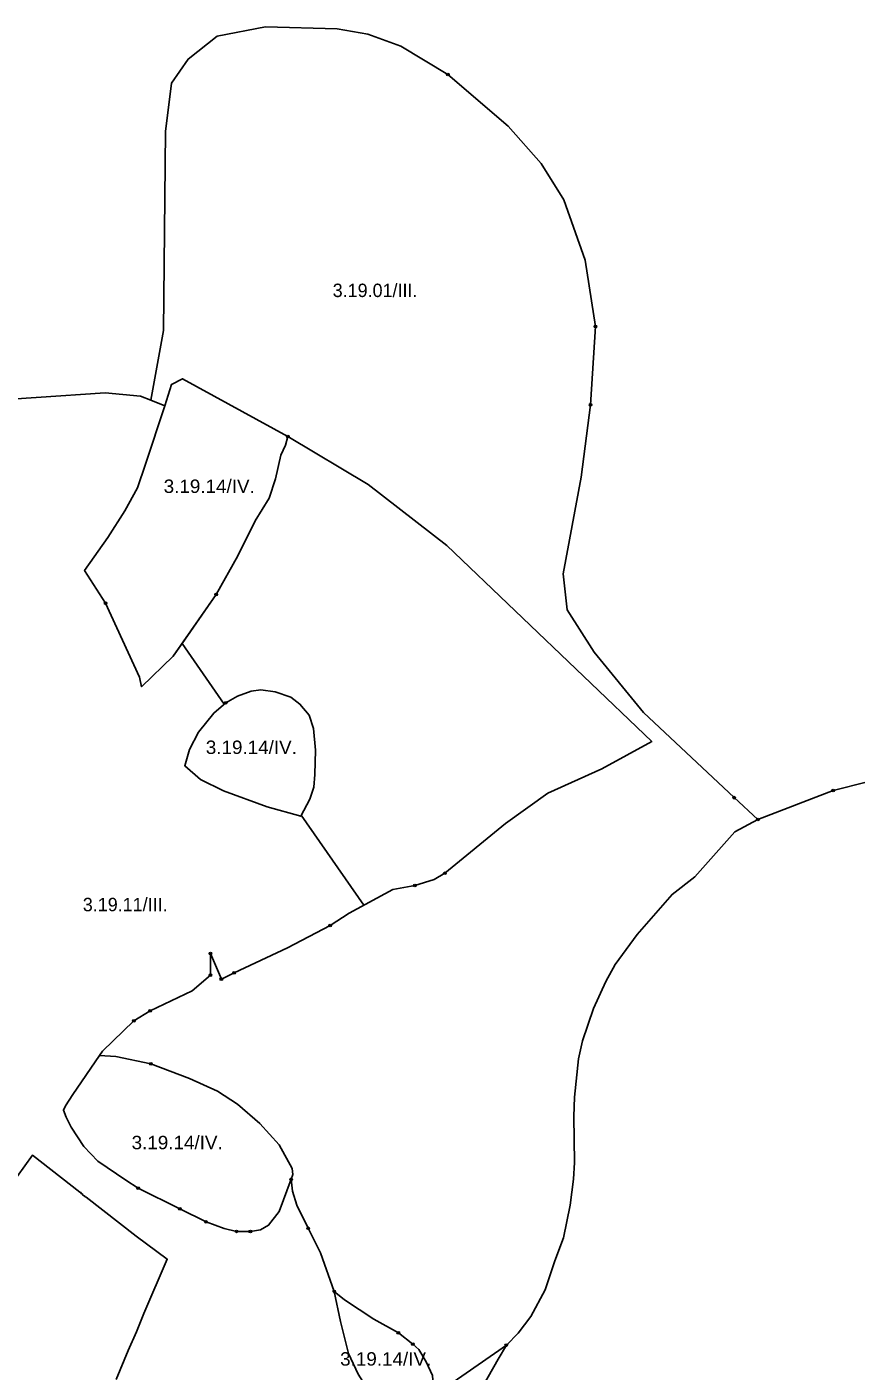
# Model space of a CAD drawing. Extents: x -650455 to -642254, y -1075222 to -1066610.
# Drawn here: x -645652 to -645034, y -1073114 to -1072112 of the extents above; entities that cross this region are included whole.
import ezdxf
from ezdxf.enums import TextEntityAlignment as Align

# ---------------------------------------------------------------- set-up
doc = ezdxf.new("R2010")
doc.units = 0
doc.header["$LTSCALE"] = 4
doc.header["$PDMODE"] = 32
doc.header["$PDSIZE"] = 2
for name, color, linetype, lineweight in [('1', 7, 'Continuous', 25), ('11', 7, 'Continuous', 13), ('12', 7, 'Continuous', 13), ('13', 7, 'Continuous', 13), ('14', 7, 'Continuous', 13)]:
    doc.layers.add(name, color=color, linetype=linetype, lineweight=lineweight)
doc.layers.add('2', color=7, linetype='Continuous')

msp = doc.modelspace()

# ---------------------------------------------------------------- linework, layer by layer
at = {"layer": '1'}
for points in [[(-645000, -1072668.218), (-645051.292, -1072681.171), (-645107.317, -1072702.887), (-645125, -1072686.501), (-645192.5, -1072623), (-645229.5, -1072578), (-645249.5, -1072546.5), (-645252.5, -1072519.501), (-645239, -1072447.501), (-645232, -1072393.5), (-645228.5, -1072335.001), (-645236, -1072285.501), (-645252, -1072240.501), (-645269, -1072213.501), (-645293.5, -1072185.5), (-645338.5, -1072147.001), (-645373.5, -1072126), (-645398, -1072117), (-645421, -1072113), (-645474.5, -1072111.501), (-645510.5, -1072118.5), (-645532, -1072135.501), (-645544.5, -1072153.5), (-645549, -1072189.5), (-645550.5, -1072338.001), (-645560, -1072390.001), (-645567.5, -1072387.001), (-645594, -1072384.5), (-645697, -1072391.501)], [(-645464.113, -1072945.509), (-645478.626, -1072929.598), (-645495.238, -1072915.084), (-645510.188, -1072905.467), (-645530.996, -1072896.025), (-645559.847, -1072885.009), (-645586.076, -1072879.478), (-645598.235, -1072878.802), (-645596, -1072875.5), (-645572.5, -1072853.001), (-645560.5, -1072845.5), (-645529, -1072830.5), (-645515.5, -1072819.001), (-645515.5, -1072802.829), (-645507.327, -1072821.847), (-645497.861, -1072817.229), (-645457.907, -1072798.52), (-645426.258, -1072781.908), (-645411.919, -1072772.641), (-645379.484, -1072754.98), (-645363.047, -1072752.008), (-645348.709, -1072747.462), (-645340.665, -1072742.916), (-645295.465, -1072705.846), (-645263.816, -1072683.115), (-645223.774, -1072664.929), (-645186.442, -1072644.646), (-645339.092, -1072498.466), (-645397.843, -1072453.003), (-645457.819, -1072417.158), (-645536.33, -1072373.968), (-645544.373, -1072378.165), (-645549.565, -1072394.297), (-645560, -1072390.001), (-645550.5, -1072338.001), (-645549, -1072189.5), (-645544.5, -1072153.5), (-645532, -1072135.501), (-645510.5, -1072118.5), (-645474.5, -1072111.501)], [(-645474.5, -1072111.501), (-645421, -1072113), (-645398, -1072117), (-645373.5, -1072126), (-645338.5, -1072147.001), (-645293.5, -1072185.5), (-645269, -1072213.501), (-645252, -1072240.501), (-645236, -1072285.501), (-645228.5, -1072335.001), (-645232, -1072393.5), (-645239, -1072447.501), (-645252.5, -1072519.501), (-645249.5, -1072546.5), (-645229.5, -1072578), (-645192.5, -1072623), (-645125, -1072686.501), (-645107.317, -1072702.887)], [(-645697, -1072391.501), (-645594, -1072384.5), (-645567.5, -1072387.001), (-645560, -1072390.001)], [(-645560, -1072390.001), (-645549.565, -1072394.297), (-645563.782, -1072437.791), (-645569.902, -1072455.277), (-645579.344, -1072472.413), (-645592.021, -1072492.346), (-645609.332, -1072517.001), (-645593.595, -1072541.481), (-645568.328, -1072596.561), (-645566.755, -1072603.73), (-645543.149, -1072580.998), (-645511.15, -1072535.011), (-645495.063, -1072506.16), (-645482.212, -1072480.106), (-645471.72, -1072463.145), (-645466.824, -1072448.632), (-645463.065, -1072430.972), (-645459.568, -1072423.628), (-645457.819, -1072417.158), (-645397.843, -1072453.003), (-645339.092, -1072498.466), (-645186.442, -1072644.646), (-645223.774, -1072664.929), (-645263.816, -1072683.115), (-645295.465, -1072705.846), (-645340.665, -1072742.916), (-645348.709, -1072747.462), (-645363.047, -1072752.008), (-645379.484, -1072754.98), (-645411.919, -1072772.641), (-645426.258, -1072781.908), (-645457.907, -1072798.52), (-645497.861, -1072817.229), (-645507.327, -1072821.847), (-645515.5, -1072802.829), (-645515.5, -1072819.001), (-645529, -1072830.5), (-645560.5, -1072845.5), (-645572.5, -1072853.001), (-645596, -1072875.5)], [(-645247.379, -1072990.622), (-645244.668, -1072971.213), (-645244.144, -1072958.624), (-645244.581, -1072924.352), (-645244.056, -1072910.014), (-645241.171, -1072881.337), (-645238.024, -1072867.873), (-645229.98, -1072843.743), (-645220.713, -1072823.634), (-645213.806, -1072810.87), (-645197.37, -1072788.488), (-645171.229, -1072758.763), (-645154.442, -1072745.474), (-645124.542, -1072712.076), (-645107.317, -1072702.887), (-645051.292, -1072681.171), (-645000, -1072668.218)], [(-645107.317, -1072702.887), (-645124.542, -1072712.076), (-645154.442, -1072745.474), (-645171.229, -1072758.763), (-645197.37, -1072788.488), (-645213.806, -1072810.87), (-645220.713, -1072823.634), (-645229.98, -1072843.743), (-645238.024, -1072867.873), (-645241.171, -1072881.337), (-645244.056, -1072910.014), (-645244.581, -1072924.352), (-645244.144, -1072958.624), (-645244.668, -1072971.213), (-645247.379, -1072990.622), (-645252.275, -1073014.927), (-645258.744, -1073032.063), (-645265.913, -1073053.571), (-645276.492, -1073073.679), (-645286.109, -1073085.919), (-645294.852, -1073094.837), (-645336.905, -1073124.213)], [(-645596, -1072875.5), (-645598.235, -1072878.802), (-645618, -1072908), (-645623.5, -1072916.501), (-645625.037, -1072919.546), (-645623.058, -1072924.876), (-645619.385, -1072932.395), (-645609.768, -1072946.733), (-645599.277, -1072957.574), (-645578.469, -1072971.913), (-645569.377, -1072977.858), (-645538.34, -1072993.245), (-645518.581, -1073003.037), (-645505.117, -1073007.933), (-645496.024, -1073010.031), (-645485.708, -1073010.206), (-645478.189, -1073008.807), (-645472.244, -1073005.485), (-645464.201, -1072995.343), (-645455.283, -1072971.213), (-645454.234, -1072979.956), (-645451.086, -1072990.447), (-645442.606, -1073007.758), (-645433.338, -1073026.118), (-645423.109, -1073054.795), (-645418.563, -1073077.351), (-645412.618, -1073101.131), (-645405.274, -1073116.694)], [(-645609.115, -1072983.715), (-645610.526, -1072983.151), (-645610.949, -1072982.163), (-645611.655, -1072982.022), (-645612.36, -1072980.893), (-645612.924, -1072980.893), (-645648.03, -1072953.171), (-645659.633, -1072969.042)], [(-645349.844, -1073117.568), (-645354.74, -1073107.426), (-645360.161, -1073098.159), (-645364.532, -1073094.137), (-645375.373, -1073085.744), (-645393.558, -1073075.428), (-645415.59, -1073061.089), (-645423.109, -1073054.795), (-645433.338, -1073026.118), (-645442.606, -1073007.758), (-645451.086, -1072990.447), (-645454.234, -1072979.956), (-645455.283, -1072971.213), (-645454.146, -1072967.716), (-645454.496, -1072963.17), (-645464.113, -1072945.509)], [(-645585.831, -1073120.596), (-645576.8, -1073098.864), (-645570.591, -1073085.034), (-645565.087, -1073071.205), (-645547.791, -1073030.888), (-645570.732, -1073013.631), (-645608.127, -1072984.42), (-645608.974, -1072984.279), (-645609.115, -1072983.715)], [(-645316.797, -1073133.48), (-645301.06, -1073105.503), (-645294.852, -1073094.837), (-645286.109, -1073085.919), (-645276.492, -1073073.679), (-645265.913, -1073053.571), (-645258.744, -1073032.063), (-645252.275, -1073014.927), (-645247.379, -1072990.622)], [(-645336.905, -1073124.213), (-645294.852, -1073094.837), (-645301.06, -1073105.503), (-645316.797, -1073133.48)]]:
    msp.add_lwpolyline(points, dxfattribs=at)
for points in [[(-645457.819, -1072417.158), (-645459.568, -1072423.628), (-645463.065, -1072430.972), (-645466.824, -1072448.632), (-645471.72, -1072463.145), (-645482.212, -1072480.106), (-645495.063, -1072506.16), (-645511.15, -1072535.011), (-645543.149, -1072580.998), (-645566.755, -1072603.73), (-645568.328, -1072596.561), (-645593.595, -1072541.481), (-645609.332, -1072517.001), (-645592.021, -1072492.346), (-645579.344, -1072472.413), (-645569.902, -1072455.277), (-645563.782, -1072437.791), (-645549.565, -1072394.297), (-645544.373, -1072378.165), (-645536.33, -1072373.968)], [(-645441.437, -1072687.696), (-645438.464, -1072678.603), (-645437.59, -1072669.336), (-645437.24, -1072651.151), (-645438.639, -1072634.889), (-645441.961, -1072624.922), (-645448.781, -1072616.704), (-645455.6, -1072611.458), (-645467.141, -1072607.611), (-645477.807, -1072606.038), (-645485.151, -1072607.087), (-645495.293, -1072610.759), (-645503.86, -1072615.655), (-645512.953, -1072623.523), (-645524.319, -1072637.687), (-645531.138, -1072650.626), (-645534.46, -1072662.866), (-645522.745, -1072672.833), (-645505.609, -1072681.401), (-645473.26, -1072693.291), (-645448.081, -1072700.285)], [(-645441.437, -1072687.696), (-645448.081, -1072700.285), (-645473.26, -1072693.291), (-645505.609, -1072681.401), (-645522.745, -1072672.833), (-645534.46, -1072662.866), (-645531.138, -1072650.626), (-645524.319, -1072637.687), (-645512.953, -1072623.523), (-645503.86, -1072615.655), (-645495.293, -1072610.759), (-645485.151, -1072607.087), (-645477.807, -1072606.038), (-645467.141, -1072607.611), (-645455.6, -1072611.458), (-645448.781, -1072616.704), (-645441.961, -1072624.922), (-645438.639, -1072634.889), (-645437.24, -1072651.151), (-645437.59, -1072669.336), (-645438.464, -1072678.603)], [(-645455.283, -1072971.213), (-645464.201, -1072995.343), (-645472.244, -1073005.485), (-645478.189, -1073008.807), (-645485.708, -1073010.206), (-645496.024, -1073010.031), (-645505.117, -1073007.933), (-645518.581, -1073003.037), (-645538.34, -1072993.245), (-645569.377, -1072977.858), (-645578.469, -1072971.913), (-645599.277, -1072957.574), (-645609.768, -1072946.733), (-645619.385, -1072932.395), (-645623.058, -1072924.876), (-645625.037, -1072919.546), (-645623.5, -1072916.501), (-645618, -1072908), (-645598.235, -1072878.802), (-645586.076, -1072879.478), (-645559.847, -1072885.009), (-645530.996, -1072896.025), (-645510.188, -1072905.467), (-645495.238, -1072915.084), (-645478.626, -1072929.598), (-645464.113, -1072945.509), (-645454.496, -1072963.17), (-645454.146, -1072967.716)], [(-645351.243, -1073131.207), (-645357.013, -1073138.376), (-645364.358, -1073140.474), (-645374.499, -1073140.125), (-645384.641, -1073137.152), (-645393.034, -1073132.256), (-645399.679, -1073125.611), (-645405.274, -1073116.694), (-645412.618, -1073101.131), (-645418.563, -1073077.351), (-645423.109, -1073054.795), (-645415.59, -1073061.089), (-645393.558, -1073075.428), (-645375.373, -1073085.744), (-645364.532, -1073094.137), (-645360.161, -1073098.159), (-645354.74, -1073107.426), (-645349.844, -1073117.568), (-645349.32, -1073124.038)]]:
    msp.add_lwpolyline(points, close=True, dxfattribs=at)
at = {"layer": '11'}
for points in [[(-646027.5, -1072126), (-646011, -1072139.501), (-645967.5, -1072184.501), (-645932, -1072243), (-645908.5, -1072283), (-645884.5, -1072309.501), (-645854, -1072327), (-645788.5, -1072351.001), (-645718.5, -1072394.001), (-645697, -1072391.501), (-645594, -1072384.5), (-645567.5, -1072387.001), (-645560, -1072390.001), (-645550.5, -1072338.001), (-645549, -1072189.5), (-645544.5, -1072153.5), (-645532, -1072135.501), (-645510.5, -1072118.5), (-645474.5, -1072111.501), (-645421, -1072113), (-645398, -1072117), (-645373.5, -1072126), (-645338.5, -1072147.001)], [(-645338.5, -1072147.001), (-645293.5, -1072185.5), (-645269, -1072213.501), (-645252, -1072240.501), (-645236, -1072285.501), (-645228.5, -1072335.001), (-645232, -1072393.5)], [(-645232, -1072393.5), (-645239, -1072447.501), (-645252.5, -1072519.501), (-645249.5, -1072546.5), (-645229.5, -1072578), (-645192.5, -1072623), (-645125, -1072686.501), (-645107.317, -1072702.887), (-645051.292, -1072681.171), (-645000, -1072668.218)]]:
    msp.add_lwpolyline(points, dxfattribs=at)
for p in [(-645338.5, -1072147.001), (-645232, -1072393.5)]:
    msp.add_point(p, dxfattribs=at)
at = {"layer": '12'}
for points in [[(-644952, -1072647.5), (-644963.5, -1072659), (-645000, -1072668.218), (-645051.292, -1072681.171)], [(-645051.292, -1072681.171), (-645107.317, -1072702.887), (-645124.542, -1072712.076), (-645154.442, -1072745.474), (-645171.229, -1072758.763), (-645197.37, -1072788.488), (-645213.806, -1072810.87), (-645220.713, -1072823.634), (-645229.98, -1072843.743), (-645238.024, -1072867.873), (-645241.171, -1072881.337), (-645244.056, -1072910.014), (-645244.581, -1072924.352), (-645244.144, -1072958.624), (-645244.668, -1072971.213), (-645247.379, -1072990.622), (-645252.275, -1073014.927), (-645258.744, -1073032.063), (-645265.913, -1073053.571), (-645276.492, -1073073.679), (-645286.109, -1073085.919), (-645294.852, -1073094.837), (-645301.06, -1073105.503), (-645316.797, -1073133.48)]]:
    msp.add_lwpolyline(points, dxfattribs=at)
msp.add_point((-645051.292, -1072681.171), dxfattribs=at)
at = {"layer": '13'}
for p, q in [((-645505.166, -1072616.785), (-645503.86, -1072615.655)), ((-645107.317, -1072702.887), (-645125, -1072686.501)), ((-645515.5, -1072802.829), (-645515.5, -1072819.001)), ((-645507.327, -1072821.847), (-645497.861, -1072817.229))]:
    msp.add_line(p, q, dxfattribs=at)
for points in [[(-645228.5, -1072335.001), (-645236, -1072285.501), (-645252, -1072240.501), (-645269, -1072213.501), (-645293.5, -1072185.5), (-645338.5, -1072147.001), (-645373.5, -1072126), (-645398, -1072117), (-645421, -1072113), (-645474.5, -1072111.501), (-645510.5, -1072118.5), (-645532, -1072135.501), (-645544.5, -1072153.5), (-645549, -1072189.5), (-645550.5, -1072338.001), (-645560, -1072390.001), (-645549.565, -1072394.297), (-645544.373, -1072378.165), (-645536.33, -1072373.968), (-645457.819, -1072417.158)], [(-645125, -1072686.501), (-645192.5, -1072623), (-645229.5, -1072578), (-645249.5, -1072546.5), (-645252.5, -1072519.501), (-645239, -1072447.501), (-645232, -1072393.5), (-645228.5, -1072335.001)], [(-645426.258, -1072781.908), (-645411.919, -1072772.641), (-645401.154, -1072766.779), (-645447.728, -1072699.616), (-645448.081, -1072700.285), (-645473.26, -1072693.291), (-645505.609, -1072681.401), (-645522.745, -1072672.833), (-645534.46, -1072662.866), (-645531.138, -1072650.626), (-645524.319, -1072637.687), (-645512.953, -1072623.523), (-645505.166, -1072616.785), (-645536.554, -1072571.521), (-645543.149, -1072580.998), (-645566.755, -1072603.73), (-645568.328, -1072596.561), (-645593.595, -1072541.481), (-645609.332, -1072517.001), (-645592.021, -1072492.346), (-645579.344, -1072472.413), (-645569.902, -1072455.277), (-645563.782, -1072437.791), (-645549.565, -1072394.297), (-645560, -1072390.001), (-645567.5, -1072387.001), (-645594, -1072384.5), (-645697, -1072391.501)], [(-645363.047, -1072752.008), (-645348.709, -1072747.462), (-645340.665, -1072742.916), (-645295.465, -1072705.846), (-645263.816, -1072683.115), (-645223.774, -1072664.929), (-645186.442, -1072644.646), (-645339.092, -1072498.466), (-645397.843, -1072453.003), (-645457.819, -1072417.158), (-645459.568, -1072423.628), (-645463.065, -1072430.972), (-645466.824, -1072448.632), (-645471.72, -1072463.145), (-645482.212, -1072480.106), (-645495.063, -1072506.16), (-645511.15, -1072535.011), (-645536.554, -1072571.521), (-645505.166, -1072616.785)], [(-645457.819, -1072417.158), (-645397.843, -1072453.003), (-645339.092, -1072498.466), (-645186.442, -1072644.646), (-645223.774, -1072664.929), (-645263.816, -1072683.115), (-645295.465, -1072705.846), (-645340.665, -1072742.916)], [(-645503.86, -1072615.655), (-645495.293, -1072610.759), (-645485.151, -1072607.087), (-645477.807, -1072606.038), (-645467.141, -1072607.611), (-645455.6, -1072611.458), (-645448.781, -1072616.704), (-645441.961, -1072624.922), (-645438.639, -1072634.889), (-645437.24, -1072651.151), (-645437.59, -1072669.336), (-645438.464, -1072678.603), (-645441.437, -1072687.696), (-645447.728, -1072699.616), (-645401.154, -1072766.779), (-645379.484, -1072754.98), (-645363.047, -1072752.008)], [(-645294.852, -1073094.837), (-645286.109, -1073085.919), (-645276.492, -1073073.679), (-645265.913, -1073053.571), (-645258.744, -1073032.063), (-645252.275, -1073014.927), (-645247.379, -1072990.622), (-645244.668, -1072971.213), (-645244.144, -1072958.624), (-645244.581, -1072924.352), (-645244.056, -1072910.014), (-645241.171, -1072881.337), (-645238.024, -1072867.873), (-645229.98, -1072843.743), (-645220.713, -1072823.634), (-645213.806, -1072810.87), (-645197.37, -1072788.488), (-645171.229, -1072758.763), (-645154.442, -1072745.474), (-645124.542, -1072712.076), (-645107.317, -1072702.887)], [(-645340.665, -1072742.916), (-645348.709, -1072747.462), (-645363.047, -1072752.008), (-645379.484, -1072754.98), (-645411.919, -1072772.641), (-645426.258, -1072781.908), (-645457.907, -1072798.52), (-645497.861, -1072817.229), (-645507.327, -1072821.847), (-645515.5, -1072802.829)], [(-645497.861, -1072817.229), (-645457.907, -1072798.52), (-645426.258, -1072781.908)], [(-645560.5, -1072845.5), (-645529, -1072830.5), (-645515.5, -1072819.001), (-645515.5, -1072802.829), (-645507.327, -1072821.847)], [(-645515.5, -1072819.001), (-645529, -1072830.5), (-645560.5, -1072845.5), (-645572.5, -1072853.001)], [(-645569.377, -1072977.858), (-645578.469, -1072971.913), (-645599.277, -1072957.574), (-645609.768, -1072946.733), (-645619.385, -1072932.395), (-645623.058, -1072924.876), (-645625.037, -1072919.546), (-645623.5, -1072916.501), (-645618, -1072908), (-645598.235, -1072878.802), (-645596, -1072875.5), (-645572.5, -1072853.001), (-645560.5, -1072845.5)], [(-645572.5, -1072853.001), (-645596, -1072875.5), (-645598.235, -1072878.802), (-645586.076, -1072879.478), (-645559.847, -1072885.009)], [(-645559.847, -1072885.009), (-645530.996, -1072896.025), (-645510.188, -1072905.467), (-645495.238, -1072915.084), (-645478.626, -1072929.598), (-645464.113, -1072945.509), (-645454.496, -1072963.17), (-645454.146, -1072967.716), (-645455.283, -1072971.213), (-645454.234, -1072979.956), (-645451.086, -1072990.447), (-645442.606, -1073007.758), (-645433.338, -1073026.118), (-645423.109, -1073054.795)], [(-645659.633, -1072969.042), (-645648.03, -1072953.171), (-645612.924, -1072980.893), (-645612.36, -1072980.893), (-645611.655, -1072982.022), (-645610.949, -1072982.163), (-645610.526, -1072983.151), (-645609.115, -1072983.715), (-645608.974, -1072984.279), (-645608.127, -1072984.42), (-645570.732, -1073013.631), (-645547.791, -1073030.888), (-645565.087, -1073071.205), (-645570.591, -1073085.034), (-645576.8, -1073098.864), (-645585.831, -1073120.596)], [(-645442.606, -1073007.758), (-645451.086, -1072990.447), (-645454.234, -1072979.956), (-645455.283, -1072971.213), (-645464.201, -1072995.343), (-645472.244, -1073005.485), (-645478.189, -1073008.807), (-645485.708, -1073010.206), (-645496.024, -1073010.031), (-645505.117, -1073007.933), (-645518.581, -1073003.037)], [(-645518.581, -1073003.037), (-645538.34, -1072993.245), (-645569.377, -1072977.858)], [(-645342.151, -1073221.608), (-645335.943, -1073197.478), (-645332.097, -1073178.418), (-645322.654, -1073149.042), (-645316.797, -1073133.48), (-645301.06, -1073105.503), (-645294.852, -1073094.837), (-645336.905, -1073124.213), (-645351.243, -1073131.207), (-645357.013, -1073138.376), (-645364.358, -1073140.474), (-645374.499, -1073140.125), (-645384.641, -1073137.152), (-645393.034, -1073132.256), (-645399.679, -1073125.611), (-645405.274, -1073116.694), (-645412.618, -1073101.131), (-645418.563, -1073077.351), (-645423.109, -1073054.795), (-645433.338, -1073026.118), (-645442.606, -1073007.758)], [(-645423.109, -1073054.795), (-645415.59, -1073061.089), (-645393.558, -1073075.428), (-645375.373, -1073085.744)], [(-645375.373, -1073085.744), (-645364.532, -1073094.137), (-645360.161, -1073098.159), (-645354.74, -1073107.426), (-645349.844, -1073117.568), (-645349.32, -1073124.038), (-645351.243, -1073131.207), (-645336.905, -1073124.213), (-645294.852, -1073094.837)]]:
    msp.add_lwpolyline(points, dxfattribs=at)
for p in [(-645228.5, -1072335.001), (-645457.819, -1072417.158), (-645503.86, -1072615.655), (-645125, -1072686.501), (-645107.317, -1072702.887), (-645340.665, -1072742.916), (-645363.047, -1072752.008), (-645426.258, -1072781.908), (-645515.5, -1072802.829), (-645515.5, -1072819.001), (-645507.327, -1072821.847), (-645497.861, -1072817.229), (-645572.5, -1072853.001), (-645560.5, -1072845.5), (-645559.847, -1072885.009), (-645569.377, -1072977.858), (-645518.581, -1073003.037), (-645442.606, -1073007.758), (-645423.109, -1073054.795), (-645375.373, -1073085.744), (-645294.852, -1073094.837)]:
    msp.add_point(p, dxfattribs=at)
at = {"layer": '14'}
msp.add_line((-645496.024, -1073010.031), (-645485.708, -1073010.206), dxfattribs=at)
for points in [[(-645511.15, -1072535.011), (-645495.063, -1072506.16), (-645482.212, -1072480.106), (-645471.72, -1072463.145), (-645466.824, -1072448.632), (-645463.065, -1072430.972), (-645459.568, -1072423.628), (-645457.819, -1072417.158), (-645536.33, -1072373.968), (-645544.373, -1072378.165), (-645549.565, -1072394.297), (-645563.782, -1072437.791), (-645569.902, -1072455.277), (-645579.344, -1072472.413), (-645592.021, -1072492.346), (-645609.332, -1072517.001), (-645593.595, -1072541.481)], [(-645593.595, -1072541.481), (-645568.328, -1072596.561), (-645566.755, -1072603.73), (-645543.149, -1072580.998), (-645543.109, -1072580.941), (-645511.15, -1072535.011)], [(-645455.283, -1072971.213), (-645454.146, -1072967.716), (-645454.496, -1072963.17), (-645464.113, -1072945.509), (-645478.626, -1072929.598), (-645495.238, -1072915.084), (-645510.188, -1072905.467), (-645530.996, -1072896.025), (-645559.847, -1072885.009), (-645586.076, -1072879.478), (-645598.235, -1072878.802), (-645618, -1072908), (-645623.5, -1072916.501), (-645625.037, -1072919.546), (-645623.058, -1072924.876), (-645619.385, -1072932.395), (-645609.768, -1072946.733), (-645599.277, -1072957.574), (-645578.469, -1072971.913), (-645569.377, -1072977.858), (-645538.34, -1072993.245)], [(-645485.708, -1073010.206), (-645478.189, -1073008.807), (-645472.244, -1073005.485), (-645464.201, -1072995.343), (-645455.283, -1072971.213)], [(-645538.34, -1072993.245), (-645518.581, -1073003.037), (-645505.117, -1073007.933), (-645496.024, -1073010.031)], [(-645364.532, -1073094.137), (-645375.373, -1073085.744), (-645393.558, -1073075.428), (-645415.59, -1073061.089), (-645423.109, -1073054.795), (-645418.563, -1073077.351), (-645412.618, -1073101.131), (-645405.274, -1073116.694), (-645399.679, -1073125.611), (-645393.034, -1073132.256), (-645384.641, -1073137.152)], [(-645384.641, -1073137.152), (-645374.499, -1073140.125), (-645364.358, -1073140.474), (-645357.013, -1073138.376), (-645351.243, -1073131.207), (-645349.32, -1073124.038), (-645349.844, -1073117.568), (-645354.74, -1073107.426), (-645360.161, -1073098.159), (-645364.532, -1073094.137)]]:
    msp.add_lwpolyline(points, dxfattribs=at)
msp.add_lwpolyline([(-645505.609, -1072681.401), (-645473.26, -1072693.291), (-645448.081, -1072700.285), (-645441.437, -1072687.696), (-645438.464, -1072678.603), (-645437.59, -1072669.336), (-645437.24, -1072651.151), (-645438.639, -1072634.889), (-645441.961, -1072624.922), (-645448.781, -1072616.704), (-645455.6, -1072611.458), (-645467.141, -1072607.611), (-645477.807, -1072606.038), (-645485.151, -1072607.087), (-645495.293, -1072610.759), (-645503.86, -1072615.655), (-645512.953, -1072623.523), (-645524.319, -1072637.687), (-645531.138, -1072650.626), (-645534.46, -1072662.866), (-645522.745, -1072672.833)], close=True, dxfattribs=at)
for p in [(-645593.595, -1072541.481), (-645511.15, -1072535.011), (-645455.283, -1072971.213), (-645538.34, -1072993.245), (-645496.024, -1073010.031), (-645485.708, -1073010.206), (-645364.532, -1073094.137)]:
    msp.add_point(p, dxfattribs=at)

# ---------------------------------------------------------------- texts
at = {"layer": '2'}
for s, p in [('3.19.01/III.', (-645392.712, -1072313.048)), ('3.19.11/III.', (-645579.002, -1072771.24))]:
    msp.add_text(s, height=10, dxfattribs=at).set_placement(p, align=Align.CENTER)
at = {"layer": '2', "width": 1.05}
for p in [(-645516.343, -1072459.176), (-645484.953, -1072653.904), (-645540.26, -1072948.768), (-645384.802, -1073110.205)]:
    msp.add_text('3.19.14/IV.', height=10, dxfattribs=at).set_placement(p, align=Align.CENTER)

doc.saveas('drawing.dxf')
